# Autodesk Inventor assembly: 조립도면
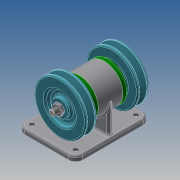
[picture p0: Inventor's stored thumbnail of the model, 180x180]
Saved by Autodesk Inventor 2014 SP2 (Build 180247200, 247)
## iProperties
Created: 2019-09
Part Number: 조립도면
Document SubType Name: Assembly
Designer: kb542-10
Author: kb542-10
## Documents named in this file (10)
- C:\Users\kb542-10\Desktop\490904V1048\답안조립품.iam
- C:\Users\kb542-10\Desktop\490904V1048\V-벨트풀리.ipt
- C:\Users\kb542-10\Desktop\490904V1048\너트 M10x1.ipt
- C:\Users\kb542-10\Desktop\490904V1048\베어링 6004.ipt
- C:\Users\kb542-10\Desktop\490904V1048\본체.ipt
- C:\Users\kb542-10\Desktop\490904V1048\볼트 M4.ipt
- C:\Users\kb542-10\Desktop\490904V1048\오일 실 17 30 5.ipt
- C:\Users\kb542-10\Desktop\490904V1048\축.ipt
- C:\Users\kb542-10\Desktop\490904V1048\커버.ipt
- C:\Users\kb542-10\Desktop\490904V1048\키 5 x 5 x 12.ipt
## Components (2 placed, 1 different names)
1. V-벨트풀리:1
2. V-벨트풀리:2
## Named parameters: d15_d14 = 0
